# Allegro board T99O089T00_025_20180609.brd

Outline 313.5 x 215.83 mm; copper layers: TOP, G02, T03, G04, T05, G06, T07, G08, P09, P10, G11, P12, G13, T14, G15, T16, G17, T18, G19, BOTTOM. Coordinates in mm from the lower left corner of the outline.
Outline path: 0,208.98 0,1 arc(0.29,0.29) 1,0 41.54,0 arc(42.24,0.29) 42.54,1 42.54,9.63 arc(42.83,10.34) 43.54,10.63 62.46,10.63 arc(62.8,11.22) 63.44,11.45 80.91,11.45 arc(81.61,11.16) 81.91,10.45 81.91,4.6 arc(82.2,3.89) 82.91,3.6 289.06,3.6 289.06,3.97 312.5,3.97 arc(313.21,4.26) 313.5,4.97 313.5,10.05 312.88,10.05 arc(312.53,10.2) 312.38,10.55 312.38,13.05 arc(312.53,13.4) 312.88,13.55 313.5,13.55 313.5,214.83 arc(313.21,215.54) 312.5,215.83 40.49,215.83 arc(39.78,215.54) 39.49,214.83 39.49,210.98 arc(39.19,210.27) 38.49,209.98 1,209.98 arc(0.29,209.69) 0,208.98 ; 288.24,13.05 arc(288.38,13.4) 288.74,13.55 290.24,13.55 arc(290.59,13.4) 290.74,13.05 290.74,10.55 arc(290.59,10.2) 290.24,10.05 288.74,10.05 arc(288.38,10.2) 288.24,10.55 288.24,13.05 ; 296.06,9.09 arc(296.76,9.79) 297.46,9.09 297.46,7.93 arc(296.76,7.24) 296.06,7.93 296.06,9.09 ; 305.66,9.09 arc(306.36,9.79) 307.06,9.09 307.06,7.93 arc(306.36,7.23) 305.66,7.93 305.66,9.09

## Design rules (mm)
net group BITS_T1_RRING: nets BITS_T1_RRING BITS_T1_RRING_XFMR
net group BITS_T1_RTIP: nets BITS_T1_RTIP BITS_T1_RTIP_XFMR
net group BITS_T1_TRING: nets BITS_T1_TRING BITS_T1_TRING_XFMR
net group BITS_T1_TRING_CMC: nets BITS_T1_TRING_CMC BITS_T1_TRING_CONN
net group BITS_T1_TTIP: nets BITS_T1_TTIP BITS_T1_TTIP_XFMR
net group BITS_T1_TTIP_CMC: nets BITS_T1_TTIP_CMC BITS_T1_TTIP_CONN
net group CAUI4_MAC_TO_PHY3_D0: nets CAUI4_MAC_TO_PHY3_DN0 CAUI4_MAC_TO_PHY3_DP0
net group CAUI4_MAC_TO_PHY3_D1: nets CAUI4_MAC_TO_PHY3_DN1 CAUI4_MAC_TO_PHY3_DP1
net group CAUI4_MAC_TO_PHY3_D2: nets CAUI4_MAC_TO_PHY3_DN2 CAUI4_MAC_TO_PHY3_DP2
net group CAUI4_MAC_TO_PHY3_D3: nets CAUI4_MAC_TO_PHY3_DN3 CAUI4_MAC_TO_PHY3_DP3
net group CAUI4_MAC_TO_PHY3_D4: nets CAUI4_MAC_TO_PHY3_DN4 CAUI4_MAC_TO_PHY3_DP4
net group CAUI4_MAC_TO_PHY3_D5: nets CAUI4_MAC_TO_PHY3_DN5 CAUI4_MAC_TO_PHY3_DP5
net group CAUI4_MAC_TO_PHY3_D6: nets CAUI4_MAC_TO_PHY3_DN6 CAUI4_MAC_TO_PHY3_DP6
net group CAUI4_MAC_TO_PHY3_D7: nets CAUI4_MAC_TO_PHY3_DN7 CAUI4_MAC_TO_PHY3_DP7
net group CAUI4_PHY3_TO_MAC_D0: nets CAUI4_PHY3_TO_MAC_DN0 CAUI4_PHY3_TO_MAC_DP0
net group CAUI4_PHY3_TO_MAC_D1: nets CAUI4_PHY3_TO_MAC_DN1 CAUI4_PHY3_TO_MAC_DP1
net group CAUI4_PHY3_TO_MAC_D2: nets CAUI4_PHY3_TO_MAC_DN2 CAUI4_PHY3_TO_MAC_DP2
net group CAUI4_PHY3_TO_MAC_D3: nets CAUI4_PHY3_TO_MAC_DN3 CAUI4_PHY3_TO_MAC_DP3
net group CAUI4_PHY3_TO_MAC_D4: nets CAUI4_PHY3_TO_MAC_DN4 CAUI4_PHY3_TO_MAC_DP4
net group CAUI4_PHY3_TO_MAC_D5: nets CAUI4_PHY3_TO_MAC_DN5 CAUI4_PHY3_TO_MAC_DP5
net group CAUI4_PHY3_TO_MAC_D6: nets CAUI4_PHY3_TO_MAC_DN6 CAUI4_PHY3_TO_MAC_DP6
net group CAUI4_PHY3_TO_MAC_D7: nets CAUI4_PHY3_TO_MAC_DN7 CAUI4_PHY3_TO_MAC_DP7
net group CAUI4_PHY3_TO_QSFP28_D0: nets CAUI4_PHY3_TO_QSFP28_DN0 CAUI4_PHY3_TO_QSFP28_DP0
net group CAUI4_PHY3_TO_QSFP28_D1: nets CAUI4_PHY3_TO_QSFP28_DN1 CAUI4_PHY3_TO_QSFP28_DP1
net group CAUI4_PHY3_TO_QSFP28_D2: nets CAUI4_PHY3_TO_QSFP28_DN2 CAUI4_PHY3_TO_QSFP28_DP2
net group CAUI4_PHY3_TO_QSFP28_D3: nets CAUI4_PHY3_TO_QSFP28_DN3 CAUI4_PHY3_TO_QSFP28_DP3
net group CAUI4_PHY3_TO_QSFP28_D4: nets CAUI4_PHY3_TO_QSFP28_DN4 CAUI4_PHY3_TO_QSFP28_DP4
net group CAUI4_PHY3_TO_QSFP28_D5: nets CAUI4_PHY3_TO_QSFP28_DN5 CAUI4_PHY3_TO_QSFP28_DP5
net group CAUI4_PHY3_TO_QSFP28_D6: nets CAUI4_PHY3_TO_QSFP28_DN6 CAUI4_PHY3_TO_QSFP28_DP6
net group CAUI4_PHY3_TO_QSFP28_D7: nets CAUI4_PHY3_TO_QSFP28_DN7 CAUI4_PHY3_TO_QSFP28_DP7
net group CAUI4_QSFP28_TO_PHY3_D0: nets CAUI4_QSFP28_TO_PHY3_DN0 CAUI4_QSFP28_TO_PHY3_DP0
net group CAUI4_QSFP28_TO_PHY3_D1: nets CAUI4_QSFP28_TO_PHY3_DN1 CAUI4_QSFP28_TO_PHY3_DP1
net group CAUI4_QSFP28_TO_PHY3_D2: nets CAUI4_QSFP28_TO_PHY3_DN2 CAUI4_QSFP28_TO_PHY3_DP2
net group CAUI4_QSFP28_TO_PHY3_D3: nets CAUI4_QSFP28_TO_PHY3_DN3 CAUI4_QSFP28_TO_PHY3_DP3
net group CAUI4_QSFP28_TO_PHY3_D4: nets CAUI4_QSFP28_TO_PHY3_DN4 CAUI4_QSFP28_TO_PHY3_DP4
net group CAUI4_QSFP28_TO_PHY3_D5: nets CAUI4_QSFP28_TO_PHY3_DN5 CAUI4_QSFP28_TO_PHY3_DP5
net group CAUI4_QSFP28_TO_PHY3_D6: nets CAUI4_QSFP28_TO_PHY3_DN6 CAUI4_QSFP28_TO_PHY3_DP6
net group CAUI4_QSFP28_TO_PHY3_D7: nets CAUI4_QSFP28_TO_PHY3_DN7 CAUI4_QSFP28_TO_PHY3_DP7
net group CLK_1PPS_SMA_IN: nets CLK_1PPS_SMA_IN CLK_1PPS_SMA_IN_DN
net group CLK_1PPS_TOD_IN: nets CLK_1PPS_TOD_IN CLK_1PPS_TOD_IN_DN
net group CLK_25M_MAC_TSPLL_DPLL_DN: nets CLK_25M_MAC_TSPLL_DPLL_DN N76605922
net group CLK_25M_MAC_TSPLL_DPLL_DP: nets CLK_25M_MAC_TSPLL_DPLL_DP N76605919
net group CLK_100M_BMC_PCIE_REF_DN: nets CLK_100M_BMC_PCIE_DN CLK_100M_BMC_PCIE_REF_DN
net group CLK_100M_BMC_PCIE_REF_DP: nets CLK_100M_BMC_PCIE_DP CLK_100M_BMC_PCIE_REF_DP
net group CLK_100M_CPU_PCIE_D: nets CLK_100M_CPU_PCIE_DN CLK_100M_CPU_PCIE_DP
net group CLK_100M_MAC_DDR_DN: nets CLK_100M_MAC_DDR_DN N70523859
net group CLK_100M_MAC_DDR_DP: nets CLK_100M_MAC_DDR_DP N70523844
net group CLK_100M_MAC_DDR_OSC_D: nets CLK_100M_MAC_DDR_OSC_DN CLK_100M_MAC_DDR_OSC_DP
net group CLK_100M_MAC_PCIE_DN: nets CLK_100M_MAC_PCIE_DN N72722010
net group CLK_100M_MAC_PCIE_DP: nets CLK_100M_MAC_PCIE_DP N72721990
net group CLK_100M_NIC1_PCIE_DN: nets CLK_100M_NIC1_PCIE_DN N72858667
net group CLK_100M_NIC1_PCIE_DP: nets CLK_100M_NIC1_PCIE_DP N72858665
net group CLK_156M25_PHY_REF0_DN: nets CLK_156M25_OUT3_REF0_DN CLK_156M25_PHY_REF0_DN
net group CLK_156M25_PHY_REF0_DP: nets CLK_156M25_OUT3_REF0_DP CLK_156M25_PHY_REF0_DP
net group CLK_156M25_PHY_REF1_DN: nets CLK_156M25_PHY_REF1_DN N73978233
net group CLK_156M25_PHY_REF1_DP: nets CLK_156M25_PHY_REF1_DP N73978235
net group CLK_PHY1_SYNCE_RCVD2_DN: nets CLK_PHY1_SYNCE_RCVD2_DN CLK_PHY1_SYNCE_REFCLK2_DN
net group CLK_PHY1_SYNCE_RCVD2_DP: nets CLK_PHY1_SYNCE_RCVD2_DP CLK_PHY1_SYNCE_REFCLK2_DP
net group CLK_PHY1_SYNCE_RCVD_DN: nets CLK_PHY1_SYNCE_RCVD_DN CLK_PHY1_SYNCE_REFCLK_DN
net group CLK_PHY1_SYNCE_RCVD_DP: nets CLK_PHY1_SYNCE_RCVD_DP CLK_PHY1_SYNCE_REFCLK_DP
net group CLK_PHY3_SYNCE_RCVDA_DN: nets CLK_PHY3_SYNCE_RCVDA_DN CLK_PHY3_SYNCE_REFCLK1_DN
net group CLK_PHY3_SYNCE_RCVDA_DP: nets CLK_PHY3_SYNCE_RCVDA_DP CLK_PHY3_SYNCE_REFCLK1_DP
net group CLK_PHY3_SYNCE_RCVDB_D: nets CLK_PHY3_SYNCE_RCVDB_DN CLK_PHY3_SYNCE_RCVDB_DP
net group DDR3_BCM_CLK_DN0: nets DDR3_BMC_CLK_DN0 DDR3_BMC_CLK_DP0
net group DDR3_BCM_DQS_DN0: nets DDR3_BMC_DQS_DN0 DDR3_BMC_DQS_DP0
net group DDR3_BCM_DQS_DN1: nets DDR3_BMC_DQS_DN1 DDR3_BMC_DQS_DP1
net group KR_CPU_TO_MAC0: nets KR_CPU_TO_MAC_DN0 KR_CPU_TO_MAC_DP0
net group KR_CPU_TO_MAC1: nets KR_CPU_TO_MAC_DN1 KR_CPU_TO_MAC_DP1
net group KR_IIO_LAN_RX0_DN: nets KR_IIO_LAN_RX0_DN KR_MAC_TO_CPU_DN0
net group KR_IIO_LAN_RX0_DP: nets KR_IIO_LAN_RX0_DP KR_MAC_TO_CPU_DP0
net group KR_IIO_LAN_RX1_DN: nets KR_IIO_LAN_RX1_DN KR_MAC_TO_CPU_DN1
net group KR_IIO_LAN_RX1_DP: nets KR_IIO_LAN_RX1_DP KR_MAC_TO_CPU_DP1
net group MAC_DDRA_CLK: nets MAC_DDRA_CLK_DN MAC_DDRA_CLK_DP
net group MAC_DDRA_DQS0: nets MAC_DDRA_DQS0_DN MAC_DDRA_DQS0_DP
net group MAC_DDRA_DQS1: nets MAC_DDRA_DQS1_DN MAC_DDRA_DQS1_DP
net group MAC_DDRA_DQS2: nets MAC_DDRA_DQS2_DN MAC_DDRA_DQS2_DP
net group MAC_DDRA_DQS3: nets MAC_DDRA_DQS3_DN MAC_DDRA_DQS3_DP
net group MAC_DDRB_CLK: nets MAC_DDRB_CLK_DN MAC_DDRB_CLK_DP
net group MAC_DDRB_DQS0: nets MAC_DDRB_DQS0_DN MAC_DDRB_DQS0_DP
net group MAC_DDRB_DQS1: nets MAC_DDRB_DQS1_DN MAC_DDRB_DQS1_DP
net group MAC_DDRB_DQS2: nets MAC_DDRB_DQS2_DN MAC_DDRB_DQS2_DP
net group MAC_DDRB_DQS3: nets MAC_DDRB_DQS3_DN MAC_DDRB_DQS3_DP
net group MAC_DDRC_CLK: nets MAC_DDRC_CLK_DN MAC_DDRC_CLK_DP
net group MAC_DDRC_DQS0: nets MAC_DDRC_DQS0_DN MAC_DDRC_DQS0_DP
net group MAC_DDRC_DQS1: nets MAC_DDRC_DQS1_DN MAC_DDRC_DQS1_DP
net group MAC_DDRC_DQS2: nets MAC_DDRC_DQS2_DN MAC_DDRC_DQS2_DP
net group MAC_DDRC_DQS3: nets MAC_DDRC_DQS3_DN MAC_DDRC_DQS3_DP
net group MAC_THERM_DIODE_D: nets MAC_THERM_DIODE_DN MAC_THERM_DIODE_DP
net group MDI_NIC1_D0: nets MDI_NIC1_DN0 MDI_NIC1_DP0
net group MDI_NIC1_D1: nets MDI_NIC1_DN1 MDI_NIC1_DP1
net group MDI_NIC1_D2: nets MDI_NIC1_DN2 MDI_NIC1_DP2
net group MDI_NIC1_D3: nets MDI_NIC1_DN3 MDI_NIC1_DP3
net group P3V3_SW: nets N75511258 P3V3_SW
net group P3V3_SW2: nets N75511286 P3V3_SW2
net group PCIE_CPU_IIO_RX_DN0: nets PCIE_CPU_IIO_RX_DN0 PCIE_MAC_TO_CPU_DN
net group PCIE_CPU_IIO_RX_DP0: nets PCIE_CPU_IIO_RX_DP0 PCIE_MAC_TO_CPU_DP
net group PCIE_CPU_PCH_RX_DN0: nets PCIE_BMC_TO_CPU_DN PCIE_CPU_PCH_RX_DN0
net group PCIE_CPU_PCH_RX_DN1: nets PCIE_CPU_PCH_RX_DN1 PCIE_NIC1_TO_CPU_DN
net group PCIE_CPU_PCH_RX_DP0: nets PCIE_BMC_TO_CPU_DP PCIE_CPU_PCH_RX_DP0
net group PCIE_CPU_PCH_RX_DP1: nets PCIE_CPU_PCH_RX_DP1 PCIE_NIC1_TO_CPU_DP
net group PCIE_CPU_TO_BMC_D: nets PCIE_CPU_TO_BMC_DN PCIE_CPU_TO_BMC_DP
net group PCIE_CPU_TO_MAC_D: nets PCIE_CPU_TO_MAC_DN PCIE_CPU_TO_MAC_DP
net group PCIE_CPU_TO_NIC1_D: nets PCIE_CPU_TO_NIC1_DN PCIE_CPU_TO_NIC1_DP
net group PCIE_CPU_TX_D4: nets TP_PCIE_IIO_TO_MB_TX2_DN TP_PCIE_IIO_TO_MB_TX2_DP
net group PCIE_CPU_TX_D5: nets TP_PCIE_IIO_TO_MB_TX3_DN TP_PCIE_IIO_TO_MB_TX3_DP
net group PD_NIF_SRD_REFCLK_Q00_D: nets PD_NIF_SRD_REFCLK_Q00_DN PD_NIF_SRD_REFCLK_Q00_DP
net group PD_NIFE_SRD_REFCLK_Q05_D: nets PD_NIFE_SRD_REFCLK_Q05_DN PD_NIFE_SRD_REFCLK_Q05_DP
net group PTP_1PPS_RS422_CONN_D: nets PTP_1PPS_RS422_CONN_DN PTP_1PPS_RS422_CONN_DP
net group PTP_1PPS_RS422_D: nets PTP_1PPS_RS422_DN PTP_1PPS_RS422_DP
net group PTP_1PPS_RS422_RL_D: nets PTP_1PPS_RS422_RL_DN PTP_1PPS_RS422_RL_DP
net group PTP_TOD_RS422_CONN_D: nets PTP_TOD_RS422_CONN_DN PTP_TOD_RS422_CONN_DP
net group PTP_TOD_RS422_D: nets PTP_TOD_RS422_DN PTP_TOD_RS422_DP
net group PTP_TOD_RS422_RL_D: nets PTP_TOD_RS422_RL_DN PTP_TOD_RS422_RL_DP
net group RJ11-40MIL: nets N77609229 N77609387
net group SFI_PHY1_TO_SFP_D0: nets SFI_PHY1_TO_SFP_DN0 SFI_PHY1_TO_SFP_DP0
net group SFI_PHY1_TO_SFP_D1: nets SFI_PHY1_TO_SFP_DN1 SFI_PHY1_TO_SFP_DP1
net group SFI_PHY1_TO_SFP_D2: nets SFI_PHY1_TO_SFP_DN2 SFI_PHY1_TO_SFP_DP2
net group SFI_PHY1_TO_SFP_D3: nets SFI_PHY1_TO_SFP_DN3 SFI_PHY1_TO_SFP_DP3
net group SFI_PHY1_TO_SFP_D4: nets SFI_PHY1_TO_SFP_DN4 SFI_PHY1_TO_SFP_DP4
net group SFI_PHY1_TO_SFP_D5: nets SFI_PHY1_TO_SFP_DN5 SFI_PHY1_TO_SFP_DP5
net group SFI_PHY1_TO_SFP_D6: nets SFI_PHY1_TO_SFP_DN6 SFI_PHY1_TO_SFP_DP6
net group SFI_PHY1_TO_SFP_D7: nets SFI_PHY1_TO_SFP_DN7 SFI_PHY1_TO_SFP_DP7
net group SFI_SFP_TO_PHY1_D0: nets SFI_SFP_TO_PHY1_DN0 SFI_SFP_TO_PHY1_DP0
net group SFI_SFP_TO_PHY1_D1: nets SFI_SFP_TO_PHY1_DN1 SFI_SFP_TO_PHY1_DP1
net group SFI_SFP_TO_PHY1_D2: nets SFI_SFP_TO_PHY1_DN2 SFI_SFP_TO_PHY1_DP2
net group SFI_SFP_TO_PHY1_D3: nets SFI_SFP_TO_PHY1_DN3 SFI_SFP_TO_PHY1_DP3
net group SFI_SFP_TO_PHY1_D4: nets SFI_SFP_TO_PHY1_DN4 SFI_SFP_TO_PHY1_DP4
net group SFI_SFP_TO_PHY1_D5: nets SFI_SFP_TO_PHY1_DN5 SFI_SFP_TO_PHY1_DP5
net group SFI_SFP_TO_PHY1_D6: nets SFI_SFP_TO_PHY1_DN6 SFI_SFP_TO_PHY1_DP6
net group SFI_SFP_TO_PHY1_D7: nets SFI_SFP_TO_PHY1_DN7 SFI_SFP_TO_PHY1_DP7
net group TP_PCIE_CPU_IIO_RX_2: nets TP_PCIE_CPU_IIO_RX_DN2 TP_PCIE_CPU_IIO_RX_DP2
net group TP_PCIE_CPU_IIO_RX_3: nets TP_PCIE_CPU_IIO_RX_DN3 TP_PCIE_CPU_IIO_RX_DP3
net group TP_PCIE_IIO_TO_MB_TX1_D: nets TP_PCIE_IIO_TO_MB_TX1_DN TP_PCIE_IIO_TO_MB_TX1_DP
net group USB2_PCH_P0_D: nets USB2_PCH_P0_DN USB2_PCH_P0_DP
net group USB2_PCH_P1_DN: nets N83584392 USB2_PCH_P1_DN
net group USB2_PCH_P1_DP: nets N83584389 USB2_PCH_P1_DP
net group USB2_PCH_P3_DN: nets USB2_BMC_HDN USB2_PCH_P3_DN
net group USB2_PCH_P3_DP: nets USB2_BMC_HDP USB2_PCH_P3_DP
net group USB11_BMC_HD: nets USB11_BMC_HDN USB11_BMC_HDP
net group USB_PCH_P2_D: nets USB_PCH_P2_DN USB_PCH_P2_DP
net group USB_PORT_DN: nets N72480405 USB_PORT_DN
net group USB_PORT_DP: nets N72480397 USB_PORT_DP
net group VDD_CORE_VS: nets VDD_CORE_VSN VDD_CORE_VSP
net group XFI_MAC_TO_PHY1_D0: nets XFI_MAC_TO_PHY1_DN0 XFI_MAC_TO_PHY1_DP0
net group XFI_MAC_TO_PHY1_D1: nets XFI_MAC_TO_PHY1_DN1 XFI_MAC_TO_PHY1_DP1
net group XFI_MAC_TO_PHY1_D2: nets XFI_MAC_TO_PHY1_DN2 XFI_MAC_TO_PHY1_DP2
net group XFI_MAC_TO_PHY1_D3: nets XFI_MAC_TO_PHY1_DN3 XFI_MAC_TO_PHY1_DP3
net group XFI_MAC_TO_PHY1_D4: nets XFI_MAC_TO_PHY1_DN4 XFI_MAC_TO_PHY1_DP4
net group XFI_MAC_TO_PHY1_D5: nets XFI_MAC_TO_PHY1_DN5 XFI_MAC_TO_PHY1_DP5
net group XFI_MAC_TO_PHY1_D6: nets XFI_MAC_TO_PHY1_DN6 XFI_MAC_TO_PHY1_DP6
net group XFI_MAC_TO_PHY1_D7: nets XFI_MAC_TO_PHY1_DN7 XFI_MAC_TO_PHY1_DP7
net group XFI_MAC_TO_SFP_D8: nets XFI_MAC_TO_SFP_DN8 XFI_MAC_TO_SFP_DP8
net group XFI_MAC_TO_SFP_D9: nets XFI_MAC_TO_SFP_DN9 XFI_MAC_TO_SFP_DP9
net group XFI_MAC_TO_SFP_D10: nets XFI_MAC_TO_SFP_DN10 XFI_MAC_TO_SFP_DP10
net group XFI_MAC_TO_SFP_D11: nets XFI_MAC_TO_SFP_DN11 XFI_MAC_TO_SFP_DP11
net group XFI_MAC_TO_SFP_D12: nets XFI_MAC_TO_SFP_DN12 XFI_MAC_TO_SFP_DP12
net group XFI_MAC_TO_SFP_D13: nets XFI_MAC_TO_SFP_DN13 XFI_MAC_TO_SFP_DP13
net group XFI_MAC_TO_SFP_D14: nets XFI_MAC_TO_SFP_DN14 XFI_MAC_TO_SFP_DP14
net group XFI_MAC_TO_SFP_D15: nets XFI_MAC_TO_SFP_DN15 XFI_MAC_TO_SFP_DP15
net group XFI_MAC_TO_SFP_D16: nets XFI_MAC_TO_SFP_DN16 XFI_MAC_TO_SFP_DP16
net group XFI_MAC_TO_SFP_D17: nets XFI_MAC_TO_SFP_DN17 XFI_MAC_TO_SFP_DP17
net group XFI_MAC_TO_SFP_D18: nets XFI_MAC_TO_SFP_DN18 XFI_MAC_TO_SFP_DP18
net group XFI_MAC_TO_SFP_D19: nets XFI_MAC_TO_SFP_DN19 XFI_MAC_TO_SFP_DP19
net group XFI_MAC_TO_SFP_D20: nets XFI_MAC_TO_SFP_DN20 XFI_MAC_TO_SFP_DP20
net group XFI_MAC_TO_SFP_D21: nets XFI_MAC_TO_SFP_DN21 XFI_MAC_TO_SFP_DP21
net group XFI_MAC_TO_SFP_D22: nets XFI_MAC_TO_SFP_DN22 XFI_MAC_TO_SFP_DP22
net group XFI_MAC_TO_SFP_D23: nets XFI_MAC_TO_SFP_DN23 XFI_MAC_TO_SFP_DP23
net group XFI_MAC_TO_SFP_DN24: nets XFI_MAC_TO_SFP_DN24 XFI_MAC_TO_SFP_DP24
net group XFI_MAC_TO_SFP_DN25: nets XFI_MAC_TO_SFP_DN25 XFI_MAC_TO_SFP_DP25
net group XFI_MAC_TO_SFP_DN26: nets XFI_MAC_TO_SFP_DN26 XFI_MAC_TO_SFP_DP26
net group XFI_MAC_TO_SFP_DN27: nets XFI_MAC_TO_SFP_DN27 XFI_MAC_TO_SFP_DP27
net group XFI_PHY1_TO_MAC_D0: nets XFI_PHY1_TO_MAC_DN0 XFI_PHY1_TO_MAC_DP0
net group XFI_PHY1_TO_MAC_D1: nets XFI_PHY1_TO_MAC_DN1 XFI_PHY1_TO_MAC_DP1
net group XFI_PHY1_TO_MAC_D2: nets XFI_PHY1_TO_MAC_DN2 XFI_PHY1_TO_MAC_DP2
net group XFI_PHY1_TO_MAC_D3: nets XFI_PHY1_TO_MAC_DN3 XFI_PHY1_TO_MAC_DP3
net group XFI_PHY1_TO_MAC_D4: nets XFI_PHY1_TO_MAC_DN4 XFI_PHY1_TO_MAC_DP4
net group XFI_PHY1_TO_MAC_D5: nets XFI_PHY1_TO_MAC_DN5 XFI_PHY1_TO_MAC_DP5
net group XFI_PHY1_TO_MAC_D6: nets XFI_PHY1_TO_MAC_DN6 XFI_PHY1_TO_MAC_DP6
net group XFI_PHY1_TO_MAC_D7: nets XFI_PHY1_TO_MAC_DN7 XFI_PHY1_TO_MAC_DP7
net group XFI_SFP_TO_MAC_D8: nets XFI_SFP_TO_MAC_DN8 XFI_SFP_TO_MAC_DP8
net group XFI_SFP_TO_MAC_D9: nets XFI_SFP_TO_MAC_DN9 XFI_SFP_TO_MAC_DP9
net group XFI_SFP_TO_MAC_D10: nets XFI_SFP_TO_MAC_DN10 XFI_SFP_TO_MAC_DP10
net group XFI_SFP_TO_MAC_D11: nets XFI_SFP_TO_MAC_DN11 XFI_SFP_TO_MAC_DP11
net group XFI_SFP_TO_MAC_D12: nets XFI_SFP_TO_MAC_DN12 XFI_SFP_TO_MAC_DP12
net group XFI_SFP_TO_MAC_D13: nets XFI_SFP_TO_MAC_DN13 XFI_SFP_TO_MAC_DP13
net group XFI_SFP_TO_MAC_D14: nets XFI_SFP_TO_MAC_DN14 XFI_SFP_TO_MAC_DP14
net group XFI_SFP_TO_MAC_D15: nets XFI_SFP_TO_MAC_DN15 XFI_SFP_TO_MAC_DP15
net group XFI_SFP_TO_MAC_D16: nets XFI_SFP_TO_MAC_DN16 XFI_SFP_TO_MAC_DP16
net group XFI_SFP_TO_MAC_D17: nets XFI_SFP_TO_MAC_DN17 XFI_SFP_TO_MAC_DP17
net group XFI_SFP_TO_MAC_D18: nets XFI_SFP_TO_MAC_DN18 XFI_SFP_TO_MAC_DP18
net group XFI_SFP_TO_MAC_D19: nets XFI_SFP_TO_MAC_DN19 XFI_SFP_TO_MAC_DP19
net group XFI_SFP_TO_MAC_D20: nets XFI_SFP_TO_MAC_DN20 XFI_SFP_TO_MAC_DP20
net group XFI_SFP_TO_MAC_D21: nets XFI_SFP_TO_MAC_DN21 XFI_SFP_TO_MAC_DP21
net group XFI_SFP_TO_MAC_D22: nets XFI_SFP_TO_MAC_DN22 XFI_SFP_TO_MAC_DP22
net group XFI_SFP_TO_MAC_D23: nets XFI_SFP_TO_MAC_DN23 XFI_SFP_TO_MAC_DP23
net group XFI_SFP_TO_MAC_DN24: nets XFI_SFP_TO_MAC_DN24 XFI_SFP_TO_MAC_DP24
net group XFI_SFP_TO_MAC_DN25: nets XFI_SFP_TO_MAC_DN25 XFI_SFP_TO_MAC_DP25
net group XFI_SFP_TO_MAC_DN26: nets XFI_SFP_TO_MAC_DN26 XFI_SFP_TO_MAC_DP26
net group XFI_SFP_TO_MAC_DN27: nets XFI_SFP_TO_MAC_DN27 XFI_SFP_TO_MAC_DP27
net group 3W: nets BITS_CLK_SEL0 BITS_CLK_SEL1 BITS_CLK_SEL2 BITS_SPI_MODE_EN BMC_ROMA0 BMC_ROMA1 BMC_ROMA2 BMC_ROMA3 BMC_ROMA4 BMC_ROMA5 BMC_ROMA6 BMC_ROMA7 BMC_ROMA8 BMC_ROMA9 BMC_ROMA10 BMC_ROMA11 BMC_ROMA12 BMC_ROMA13 BMC_ROMA14 BMC_ROMA15 BMC_ROMA16 BMC_ROMA17 BMC_ROMA18 BMC_ROMA19 BMC_ROMA20 BMC_ROMA21 BMC_ROMA22 BMC_ROMA23 BMC_ROMCS0_N BMC_ROMD0 BMC_ROMD1 BMC_ROMD5 BMC_ROMD6 BMC_ROMD7 BMC_SIOS3_N BMC_SIOS5_N BMC_SIOSPWRREQ_N CPLD_CONF_DONE CPLD_CONFIG_EN CPLD_CRC_ERROR CPLD_STATUS_N EEPROM_ADDR0 EEPROM_ADDR0_SYS EEPROM_ADDR1 EEPROM_ADDR1_SYS EEPROM_WP EEPROM_WP_SYS FAN1_PRSNT_N FAN1_PWM_CTRL FAN1_TACH_INT_INLET FAN1_TACH_INT_INLET_N FAN2_PRSNT_N FAN2_PWM_CTRL FAN2_TACH_INT_INLET FAN2_TACH_INT_INLET_N FAN3_PWM_CTRL FAN3_TACH_INT_INLET FAN3_TACH_INT_INLET_N FAN4_TACH_INT_INLET FAN4_TACH_INT_INLET_N FAN5_TACH_IN FAN5_TACH_INT_INLET FAN5_TACH_INT_INLET_N HWM_FAN1_PRSNT_N HWM_FAN1_PWM_CTRL HWM_FAN2_PRSNT_N HWM_FAN2_PWM_CTRL HWM_FAN3_PWM_CTRL HWM_FAN5_TACH_IN IN_SEL0 IN_SEL1 JITTER_A0 JITTER_A1 JTAG_BITS_RST_N JTAG_BMC_RST_N JTAG_BMC_RTCK JTAG_BMC_RTCK_SR JTAG_BMC_TCK JTAG_BMC_TCK_SR JTAG_BMC_TDI JTAG_BMC_TDO JTAG_BMC_TMS JTAG_BMC_TRST_N JTAG_BRCM_OE JTAG_BRCM_RST_N JTAG_BRCM_TDI JTAG_BRCM_TMS JTAG_CHAIN_RST_N JTAG_CHAIN_TCK JTAG_CHAIN_TCK_BUFF JTAG_CHAIN_TDI JTAG_CHAIN_TDO JTAG_CHAIN_TMS JTAG_CPLD_EN JTAG_CPLD_TDI JTAG_CPLD_TDO JTAG_CPLD_TMS JTAG_MAC_TCE JTAG_MAC_TCK JTAG_MAC_TDI JTAG_NIC1_TCK JTAG_NIC1_TDI JTAG_NIC1_TMS JTAG_PHY1_TCK JTAG_PHY1_TDI JTAG_PHY1_TDO JTAG_PHY3_TCK JTAG_PHY3_TDI JTAG_SMU_RST_N MAC_PUC00_COREPLL_FREQ0 MAC_PUC01_COREPLL_FREQ1 MAC_PUC02_COREPLL_FREQ2 MAC_PUC03_COREPLL_FREQ3 MAC_PUC04_PD MAC_PUC05_I2C_ADDR0 MAC_PUC06_I2C_ADDR1 MAC_PUC07_PCIE_DIS MAC_PUC08_PD MAC_PUC09_PD MAC_PUC10_COREPLL_SEL MAC_PUC11_COREPLL_SEL MAC_VCORE_ROV0 MAC_VCORE_ROV1 MAC_VCORE_ROV2 PHY1_PRTAD0 PHY1_PRTAD1 PHY1_PRTAD3 PHY1_PRTAD4 PHY3_PRTAD1 PHY3_PRTAD2 PHY3_PRTAD3 PHY3_PRTAD4 PHY3_SERBOOT UART_BMC_CONSOLE_RX UART_BMC_CONSOLE_RX_OUT UART_BMC_CONSOLE_TX UART_BMC_TO_CPU UART_BMC_TXD1 UART_BMC_TXD5 UART_CPU_BMC_MUX_SEL UART_CPU_CONSOLE_RX UART_CPU_CONSOLE_RX_OUT UART_CPU_CONSOLE_TX UART_CPU_TO_BMC UART_MAC_TX0 UART_MAC_TX1 UART_RS232_RX UART_RS232_RX_IN UART_RS232_RX_RJ45 UART_RS232_RX_USB UART_RS232_TX UART_RS232_TX_OUT UART_RS232_TX_RJ45 UART_RS232_TX_USB UART_TOD_GNSS_RXD UART_TOD_GNSS_TXD UART_TOD_RS422_RXD UART_TOD_RS422_TXD
net group 3W-I2C: nets BITS_REFR BMC_ADCREXT BMC_ADCVREFN BMC_ADCVREFP BMC_DACRSET BMC_I2C9_SCL BMC_OSC_OE BMC_PCIE_REXT BMC_PWRGD BMC_SFLA_CS0_N BMC_SFLA_HOLD_N BMC_SFLA_SCK BMC_SFLA_WP_N BMC_SPI_CS1_N BUILD_ID0 BUILD_ID1 CLK_DDR_SRC_SEL CLK_LPC_OE CLK_NIC1_OSC_OE CPLD_OSC_OE CPU_PRSNT_L CPU_PWRGD CPU_TO_BMC_PWRGD CPU_TO_CPLD_PWRGD HW_REV_ID0 HW_REV_ID1 HWM_JTAG_TRCK HWM_JTAG_TRST_N I2C0_HWM_SCL I2C0_HWM_SDA I2C0_MISC_SCL I2C0_MISC_SDA I2C0_PCH_SCL I2C0_PCH_SDA I2C0_PSU1_SCL I2C0_PSU1_SDA I2C0_PSU2_SCL I2C0_PSU2_SDA I2C0_PWR_SCL I2C0_PWR_SDA I2C0_SYS_SCL I2C0_SYS_SDA I2C1_BMC_SCL I2C1_BMC_SDA I2C2_BMC_SCL I2C2_BMC_SDA I2C2_PCH_SCL I2C2_PCH_SDA I2C3_BMC_SCL I2C3_BMC_SDA I2C4_BMC_SCL I2C4_BMC_SDA I2C_CPLD_SCL I2C_CPLD_SDA I2C_GNSS_SCL I2C_GNSS_SDA I2C_HWM_CLK I2C_HWM_DAT I2C_IOP_ABS0_ADDR0 I2C_IOP_ABS0_ADDR1 I2C_IOP_ABS0_ADDR2 I2C_IOP_ABS0_SCL I2C_IOP_ABS0_SDA I2C_IOP_ABS1_ADDR0 I2C_IOP_ABS1_ADDR1 I2C_IOP_ABS1_ADDR2 I2C_IOP_ABS1_SCL I2C_IOP_ABS1_SDA I2C_IOP_ALRM_ADDR0 I2C_IOP_ALRM_ADDR1 I2C_IOP_ALRM_ADDR2 I2C_IOP_ALRM_SCL I2C_IOP_ALRM_SDA I2C_IOP_DIS0_ADDR0 I2C_IOP_DIS0_ADDR1 I2C_IOP_DIS0_ADDR2 I2C_IOP_DIS0_SCL I2C_IOP_DIS0_SDA I2C_IOP_DIS1_ADDR0 I2C_IOP_DIS1_ADDR1 I2C_IOP_DIS1_ADDR2 I2C_IOP_DIS1_SCL I2C_IOP_DIS1_SDA I2C_IOP_FLT0_ADDR0 I2C_IOP_FLT0_ADDR1 I2C_IOP_FLT0_ADDR2 I2C_IOP_FLT0_SCL I2C_IOP_FLT0_SDA I2C_IOP_FLT1_ADDR0 I2C_IOP_FLT1_ADDR1 I2C_IOP_FLT1_ADDR2 I2C_IOP_FLT1_SCL I2C_IOP_FLT1_SDA I2C_IOP_FLT2_ADDR0 I2C_IOP_FLT2_ADDR1 I2C_IOP_FLT2_ADDR2 I2C_IOP_LOS0_ADDR0 I2C_IOP_LOS0_ADDR1 I2C_IOP_LOS0_ADDR2 I2C_IOP_LOS0_SCL I2C_IOP_LOS0_SDA I2C_IOP_LOS1_ADDR0 I2C_IOP_LOS1_ADDR1 I2C_IOP_LOS1_ADDR2 I2C_IOP_LOS1_SCL I2C_IOP_LOS1_SDA I2C_IOP_QSFP28_SCL I2C_IOP_QSFP28_SDA I2C_IOP_RS0_ADDR0 I2C_IOP_RS0_ADDR1 I2C_IOP_RS0_ADDR2 I2C_IOP_RS0_SCL I2C_IOP_RS0_SDA I2C_IOP_RS1_ADDR0 I2C_IOP_RS1_ADDR1 I2C_IOP_RS1_ADDR2 I2C_IOP_RS1_SCL I2C_IOP_RS1_SDA I2C_IOP_VMG_SCL I2C_IOP_VMG_SDA I2C_MAC_SCL I2C_MAC_SDA I2C_MGMT_MUX1_ADDR0 I2C_MGMT_MUX1_ADDR1 I2C_MGMT_MUX1_ADDR2 I2C_MGMT_MUX1_SCL I2C_MGMT_MUX1_SDA I2C_MGMT_SCL I2C_MGMT_SDA I2C_MUX3_ADDR0 I2C_MUX3_ADDR1 I2C_MUX3_ADDR2 I2C_MUX4_ADDR0 I2C_MUX4_ADDR1 I2C_MUX4_ADDR2 I2C_MUX5_ADDR0 I2C_MUX5_ADDR1 I2C_MUX5_ADDR2 I2C_MUX6_ADDR0 I2C_MUX6_ADDR1 I2C_MUX6_ADDR2 I2C_QSFP28_MUX7_SCL I2C_QSFP28_MUX7_SDA I2C_QSFP28_P1_SCL I2C_QSFP28_P1_SDA I2C_QSFP28_P2_SCL I2C_QSFP28_P2_SDA I2C_QSFP28_P3_SCL I2C_QSFP28_P3_SDA I2C_QSFP28_P4_SCL I2C_QSFP28_P4_SDA I2C_SFP+_MUX2_SCL I2C_SFP+_MUX2_SDA I2C_SFP+_MUX3_SCL I2C_SFP+_MUX3_SDA I2C_SFP+_MUX4_SCL I2C_SFP+_MUX4_SDA I2C_SFP+_MUX5_SCL I2C_SFP+_MUX5_SDA I2C_SFP+_MUX6_SCL I2C_SFP+_MUX6_SDA I2C_SFP+_P00_SCL I2C_SFP+_P00_SDA I2C_SFP+_P01_SCL I2C_SFP+_P01_SDA I2C_SFP+_P02_SCL I2C_SFP+_P02_SDA I2C_SFP+_P03_SCL I2C_SFP+_P03_SDA I2C_SFP+_P04_SCL I2C_SFP+_P04_SDA I2C_SFP+_P05_SCL I2C_SFP+_P05_SDA I2C_SFP+_P06_SCL I2C_SFP+_P06_SDA I2C_SFP+_P07_SCL I2C_SFP+_P07_SDA I2C_SFP+_P08_SCL I2C_SFP+_P08_SDA I2C_SFP+_P09_SCL I2C_SFP+_P09_SDA I2C_SFP+_P10_SCL I2C_SFP+_P10_SDA I2C_SFP+_P11_SCL I2C_SFP+_P11_SDA I2C_SFP+_P12_SCL I2C_SFP+_P12_SDA I2C_SFP+_P13_SCL I2C_SFP+_P13_SDA I2C_SFP+_P14_SCL I2C_SFP+_P14_SDA I2C_SFP+_P15_SCL I2C_SFP+_P15_SDA I2C_SFP+_P16_SCL I2C_SFP+_P16_SDA I2C_SFP+_P17_SCL I2C_SFP+_P17_SDA I2C_SFP+_P18_SCL I2C_SFP+_P18_SDA I2C_SFP+_P19_SCL I2C_SFP+_P19_SDA I2C_SFP+_P20_SCL I2C_SFP+_P20_SDA I2C_SFP+_P21_SCL I2C_SFP+_P21_SDA I2C_SFP+_P22_SCL I2C_SFP+_P22_SDA I2C_SFP+_P23_SCL I2C_SFP+_P23_SDA I2C_SFP+_P24_SCL I2C_SFP+_P24_SDA I2C_SFP+_P25_SCL I2C_SFP+_P25_SDA I2C_SFP+_P26_SCL I2C_SFP+_P26_SDA I2C_SFP+_P27_SCL I2C_SFP+_P27_SDA I2C_SFP_IOP0_SCL I2C_SFP_IOP0_SDA I2C_SFP_IOP1_SCL I2C_SFP_IOP1_SDA I2C_SFP_IOP2_SCL I2C_SFP_IOP2_SDA I2C_SFP_MUX2_ADDR0 I2C_SFP_MUX2_ADDR1 I2C_SFP_MUX2_ADDR2 I2C_SFP_MUX7_ADDR0 I2C_SFP_MUX7_ADDR1 I2C_SFP_MUX7_ADDR2 I2C_SFP_MUX_SCL I2C_SFP_MUX_SDA I2C_SMU_EEPROM_SCL I2C_SMU_EEPROM_SDA I2C_SMU_SCL I2C_SMU_SDA I2C_TSEN1_ADDR0 I2C_TSEN1_ADDR1 I2C_TSEN_SCL I2C_TSEN_SDA INT1_GNSS_N INT_BITS_N INT_BMC_LOAD_DEFAULT_N INT_BMC_TO_CPU_N INT_CHIP_CPLD_TO_CPU_N INT_CJA_INTR_N INT_CJA_LOL_N INT_CPLD_NMI_N INT_CPU_LOAD_DEFAULT_N INT_CPU_TO_BMC_N INT_FAN1_N INT_FAN2_N INT_FAN3_N INT_FAN4_N INT_FAN5_N INT_FAN_CARD_N INT_LOAD_DEFAULT_N INT_MAC_N INT_NIC1_ARLT_N INT_NMI_CPLD_TO_BMC_N INT_NMI_CPLD_TO_CPU_N INT_PHY1_N INT_PHY3_N INT_PSU1_N INT_PSU2_N INT_PTP_CPLD_TO_CPU_N INT_QSFP28_N INT_SFP+_ABS_N0 INT_SFP+_ABS_N1 INT_SFP+_DIS_N0 INT_SFP+_DIS_N1 INT_SFP+_DIS_N2 INT_SFP+_FLT_N0 INT_SFP+_FLT_N1 INT_SFP+_LOS_N0 INT_SFP+_LOS_N1 INT_SFP+_RS_N0 INT_SFP+_RS_N1 INT_SFP_CPLD_TO_CPU_N INT_SMU_N INT_TSEN_NMI_N INT_VCORE_ALRT_N INT_VCORE_VR_FAULT_N LED0_NIC1_LINK_FE LED1_NIC1_ACT_N LED2_NIC1_LINK_GE LED_ETH_STAT_CLR_N LED_FAN_CLR_N LED_FAN_SCL LED_FAN_SCLK LED_FAN_SDA LED_FAN_SDAT LED_INIT_CLR_N LED_MAC_SCLK LED_MAC_SCLK_SR LED_MAC_SDAT LED_MAC_SDAT_SR LED_NIC1_LINK_FE LED_NIC1_LINK_GE LED_PORT_BUF0_EN_N LED_PORT_BUF1_EN_N LED_PORT_CLK0 LED_PORT_CLK1 LED_PORT_CLK2 LED_PORT_CLK3 LED_PORT_CLK4 LED_PORT_CLK5 LED_PORT_CLK6 LED_PORT_CLK7 LED_PORT_CLK8 LED_PORT_CLK9 LED_PORT_CLK10 LED_PORT_CLK_BUF0 LED_PORT_CLK_BUF1 LED_PORT_CLK_BUF2 LED_PORT_CLK_IN0 LED_PORT_CLK_IN1 LED_PORT_CLK_IN2 LED_PORT_CLR_N0 LED_PORT_CLR_N1 LED_PORT_STAT_CLK0 LED_PORT_STAT_CLK1 LED_PORT_STAT_CLK2 LED_PORT_STAT_CLK3 LED_PORT_STAT_CLK4 LED_PORT_STAT_CLK5 LED_PORT_STAT_CLK6 LED_PORT_STAT_CLK7 LED_PORT_STAT_CLK8 LED_PORT_STAT_CLR_N0 LED_PORT_STAT_CLR_N1 LED_QSFP28_GRN_P1 LED_QSFP28_GRN_P2 LED_QSFP28_GRN_P3 LED_QSFP28_GRN_P4 LED_QSFP28_GRN_P5 LED_QSFP28_GRN_P6 LED_QSFP28_GRN_P7 LED_QSFP28_GRN_P8 LED_QSFP28_GRN_SR_P1 LED_QSFP28_GRN_SR_P2 LED_QSFP28_GRN_SR_P3 LED_QSFP28_GRN_SR_P4 LED_QSFP28_GRN_SR_P5 LED_QSFP28_GRN_SR_P6 LED_QSFP28_GRN_SR_P7 LED_QSFP28_GRN_SR_P8 LED_QSFP28_YEL_P1 LED_QSFP28_YEL_P2 LED_QSFP28_YEL_P3 LED_QSFP28_YEL_P4 LED_QSFP28_YEL_P5 LED_QSFP28_YEL_P6 LED_QSFP28_YEL_P7 LED_QSFP28_YEL_P8 LED_QSFP28_YEL_SR_P1 LED_QSFP28_YEL_SR_P2 LED_QSFP28_YEL_SR_P3 LED_QSFP28_YEL_SR_P4 LED_QSFP28_YEL_SR_P5 LED_QSFP28_YEL_SR_P6 LED_QSFP28_YEL_SR_P7 LED_QSFP28_YEL_SR_P8 LED_SFP+_GRN_P0 LED_SFP+_GRN_P1 LED_SFP+_GRN_P2 LED_SFP+_GRN_P3 LED_SFP+_GRN_P4 LED_SFP+_GRN_P5 LED_SFP+_GRN_P6 LED_SFP+_GRN_P7 LED_SFP+_GRN_P8 LED_SFP+_GRN_P9 LED_SFP+_GRN_P10 LED_SFP+_GRN_P11 LED_SFP+_GRN_P12 LED_SFP+_GRN_P13 LED_SFP+_GRN_P14 LED_SFP+_GRN_P15 LED_SFP+_GRN_P16 LED_SFP+_GRN_P17 LED_SFP+_GRN_P18 LED_SFP+_GRN_P19 LED_SFP+_GRN_P20 LED_SFP+_GRN_P21 LED_SFP+_GRN_P22 LED_SFP+_GRN_P23 LED_SFP+_GRN_P24 LED_SFP+_GRN_P25 LED_SFP+_GRN_P26 LED_SFP+_GRN_P27 LED_SFP+_GRN_SR_P0 LED_SFP+_GRN_SR_P1 LED_SFP+_GRN_SR_P2 LED_SFP+_GRN_SR_P3 LED_SFP+_GRN_SR_P4 LED_SFP+_GRN_SR_P5 LED_SFP+_GRN_SR_P6 LED_SFP+_GRN_SR_P7 LED_SFP+_GRN_SR_P8 LED_SFP+_GRN_SR_P9 LED_SFP+_GRN_SR_P10 LED_SFP+_GRN_SR_P11 LED_SFP+_GRN_SR_P12 LED_SFP+_GRN_SR_P13 LED_SFP+_GRN_SR_P14 LED_SFP+_GRN_SR_P15 LED_SFP+_GRN_SR_P16 LED_SFP+_GRN_SR_P17 LED_SFP+_GRN_SR_P18 LED_SFP+_GRN_SR_P19 LED_SFP+_GRN_SR_P20 LED_SFP+_GRN_SR_P21 LED_SFP+_GRN_SR_P22 LED_SFP+_GRN_SR_P23 LED_SFP+_GRN_SR_P24 LED_SFP+_GRN_SR_P25 LED_SFP+_GRN_SR_P26 LED_SFP+_GRN_SR_P27 LED_SFP+_YEL_P0 LED_SFP+_YEL_P1 LED_SFP+_YEL_P2 LED_SFP+_YEL_P3 LED_SFP+_YEL_P4 LED_SFP+_YEL_P5 LED_SFP+_YEL_P6 LED_SFP+_YEL_P7 LED_SFP+_YEL_P8 LED_SFP+_YEL_P9 LED_SFP+_YEL_P10 LED_SFP+_YEL_P11 LED_SFP+_YEL_P12 LED_SFP+_YEL_P13 LED_SFP+_YEL_P14 LED_SFP+_YEL_P15 LED_SFP+_YEL_P16 LED_SFP+_YEL_P17 LED_SFP+_YEL_P18 LED_SFP+_YEL_P19 LED_SFP+_YEL_P20 LED_SFP+_YEL_P21 LED_SFP+_YEL_P22 LED_SFP+_YEL_P23 LED_SFP+_YEL_P24 LED_SFP+_YEL_P25 LED_SFP+_YEL_P26 LED_SFP+_YEL_P27 LED_SFP+_YEL_SR_P0 LED_SFP+_YEL_SR_P1 LED_SFP+_YEL_SR_P2 LED_SFP+_YEL_SR_P3 LED_SFP+_YEL_SR_P4 LED_SFP+_YEL_SR_P5 LED_SFP+_YEL_SR_P6 LED_SFP+_YEL_SR_P7 LED_SFP+_YEL_SR_P8 LED_SFP+_YEL_SR_P9 LED_SFP+_YEL_SR_P10 LED_SFP+_YEL_SR_P11 LED_SFP+_YEL_SR_P12 LED_SFP+_YEL_SR_P13 LED_SFP+_YEL_SR_P14 LED_SFP+_YEL_SR_P15 LED_SFP+_YEL_SR_P16 LED_SFP+_YEL_SR_P17 LED_SFP+_YEL_SR_P18 LED_SFP+_YEL_SR_P19 LED_SFP+_YEL_SR_P20 LED_SFP+_YEL_SR_P21 LED_SFP+_YEL_SR_P22 LED_SFP+_YEL_SR_P23 LED_SFP+_YEL_SR_P24 LED_SFP+_YEL_SR_P25 LED_SFP+_YEL_SR_P26 LED_SFP+_YEL_SR_P27 LED_SYS_STAT_CLR_N LED_SYS_STAT_SCL LED_SYS_STAT_SCLK LED_SYS_STAT_SDA LED_SYS_STAT_SDAT LPC_BMC_FRAME_N LPC_BMC_LAD0 LPC_BMC_LAD1 LPC_BMC_LAD2 LPC_BMC_LAD3 LPC_BMC_SERIRQ_N LPC_FRAME_PCH_N LPC_LAD0_PCH LPC_LAD1_PCH LPC_LAD2_PCH LPC_LAD3_PCH LPC_PDN_N LPC_PME_N LPC_SERIRQ_PCH_N MAC_RES_CAL0 MAC_RES_CAL1 MIIM_BMC1_MDC MIIM_BMC1_MDIO MIIM_BMC2_MDC MIIM_BMC2_MDIO MIIM_MAC_ST_MDC0 MIIM_MAC_ST_MDC1 MIIM_MAC_ST_MDC2 MIIM_MAC_ST_MDIO0 MIIM_MAC_ST_MDIO2 MIIM_PHY1_MDC MIIM_PHY1_MDIO MIIM_PHY2_MDC MIIM_PHY3_MDC MIIM_PHY3_MDIO NCSI_BMC_CSRDV NCSI_BMC_RXD0 NCSI_BMC_RXD1 NCSI_BMC_TXD0 NCSI_BMC_TXD1 NCSI_BMC_TXEN NCSI_NIC1_CSRDV NCSI_NIC1_RXD0 NCSI_NIC1_RXD1 NIC1_NVM_CLK NIC1_NVM_CLK_ST NIC1_NVM_CS_N NIC1_NVM_CS_ST_N NIC1_NVM_HOLD_N NIC1_NVM_SI NIC1_NVM_SI_ST NIC1_NVM_SO NIC1_NVM_SO_OUT NIC1_NVM_WP_N NIC1_RSET NMI_BMC_TO_CPU_N PCIE_BMC_WAKE_N PCIE_NIC1_WAKE_N PSU1_ALRT_N PSU1_PRSNT_N PSU1_PSON_N PSU1_PWRGD PSU1_PWROK PSU2_ALRT_N PSU2_PRSNT_N PSU2_PSON_N PSU2_PWRGD PSU2_PWROK PTP_1PPS_RS422_RXD_EN_N PTP_1PPS_RS422_RXD_IN PTP_1PPS_RS422_TXD_EN PTP_OSC_OE PTP_TOD_RS422_RXD_EN_N PTP_TOD_RS422_RXD_IN PTP_TOD_RS422_TXD_EN PWR_OFF_MAC PWREN_P1V0 PWREN_P1V2 PWREN_P1V8 PWREN_P1V25 PWREN_P3V3 PWREN_VCORE PWROK_SYS_DC QSFP28_P1_INT_N QSFP28_P1_LPMODE QSFP28_P1_PRSNT_N QSFP28_P1_RST_N QSFP28_P2_INT_N QSFP28_P2_MODSEL_N QSFP28_P2_PRSNT_N QSFP28_P2_RST_N QSFP28_PWR_OC_N QSFP_PWR_ILIM ROV_EN ROV_PG RST_BITS_N RST_BMC_DDR3_N RST_BMC_PCIE_N RST_BMC_SYS_L RST_BMC_TO_CPU_N RST_BMC_WDT_L RST_CJA_N RST_CPLD_TO_BMC_SYS_L RST_CPLD_TO_CPU_N RST_CPU_PWRBTN_N RST_CPU_SYS_N RST_CPU_TO_BMC_N RST_CPU_TO_MB_I2C_N RST_GNSS_N RST_HWM_N RST_I2C_MUX1_N RST_I2C_MUX2_N RST_I2C_MUX3_N RST_I2C_MUX4_N RST_I2C_MUX5_N RST_I2C_MUX6_N RST_I2C_MUX7_N RST_MAC_N RST_NIC1_N RST_NIC1_PCIE_N RST_PHY1_N RST_PHY3_N RST_SMU_N RST_SW_BTN_N RST_SW_TO_CP2104 RST_USB_BRIDGE_N RTC_BAT_SENSE_EN_N SFP28_PWR_OC_N SFP+_P00_MOD_ABS SFP+_P00_RATE_SEL SFP+_P00_RATE_SEL_OUT SFP+_P00_RX_LOS SFP+_P00_TX_DIS SFP+_P00_TX_FLT SFP+_P01_MOD_ABS SFP+_P01_RATE_SEL SFP+_P01_RATE_SEL_OUT SFP+_P01_RX_LOS SFP+_P01_TX_DIS SFP+_P01_TX_FLT SFP+_P02_MOD_ABS SFP+_P02_RATE_SEL SFP+_P02_RATE_SEL_OUT SFP+_P02_RX_LOS SFP+_P02_TX_DIS SFP+_P02_TX_FLT SFP+_P03_MOD_ABS SFP+_P03_RATE_SEL SFP+_P03_RATE_SEL_OUT SFP+_P03_RX_LOS SFP+_P03_TX_DIS SFP+_P03_TX_FLT SFP+_P04_MOD_ABS SFP+_P04_RATE_SEL SFP+_P04_RATE_SEL_OUT SFP+_P04_RX_LOS SFP+_P04_TX_DIS SFP+_P04_TX_FLT SFP+_P05_MOD_ABS SFP+_P05_RATE_SEL SFP+_P05_RATE_SEL_OUT SFP+_P05_RX_LOS SFP+_P05_TX_DIS SFP+_P05_TX_FLT SFP+_P06_MOD_ABS SFP+_P06_RATE_SEL SFP+_P06_RATE_SEL_OUT SFP+_P06_RX_LOS SFP+_P06_TX_DIS SFP+_P06_TX_FLT SFP+_P07_MOD_ABS SFP+_P07_RATE_SEL SFP+_P07_RATE_SEL_OUT SFP+_P07_RX_LOS SFP+_P07_TX_DIS SFP+_P07_TX_FLT SFP+_P08_MOD_ABS SFP+_P08_RATE_SEL SFP+_P08_RATE_SEL_OUT SFP+_P08_RX_LOS SFP+_P08_TX_DIS SFP+_P08_TX_FLT SFP+_P09_MOD_ABS SFP+_P09_RATE_SEL SFP+_P09_RATE_SEL_OUT SFP+_P09_RX_LOS SFP+_P09_TX_DIS SFP+_P09_TX_FLT SFP+_P10_MOD_ABS SFP+_P10_RATE_SEL SFP+_P10_RATE_SEL_OUT SFP+_P10_RX_LOS SFP+_P10_TX_DIS SFP+_P10_TX_FLT SFP+_P11_MOD_ABS SFP+_P11_RATE_SEL SFP+_P11_RATE_SEL_OUT SFP+_P11_RX_LOS SFP+_P11_TX_DIS SFP+_P11_TX_FLT SFP+_P12_MOD_ABS SFP+_P12_RATE_SEL SFP+_P12_RATE_SEL_OUT SFP+_P12_RX_LOS SFP+_P12_TX_DIS SFP+_P12_TX_FLT SFP+_P13_MOD_ABS SFP+_P13_RATE_SEL SFP+_P13_RATE_SEL_OUT SFP+_P13_RX_LOS SFP+_P13_TX_DIS SFP+_P13_TX_FLT SFP+_P14_MOD_ABS SFP+_P14_RATE_SEL SFP+_P14_RATE_SEL_OUT SFP+_P14_RX_LOS SFP+_P14_TX_DIS SFP+_P14_TX_FLT SFP+_P15_MOD_ABS SFP+_P15_RATE_SEL SFP+_P15_RATE_SEL_OUT SFP+_P15_RX_LOS SFP+_P15_TX_DIS SFP+_P15_TX_FLT SFP+_P16_MOD_ABS SFP+_P16_RATE_SEL SFP+_P16_RATE_SEL_OUT SFP+_P16_RX_LOS SFP+_P16_TX_DIS SFP+_P16_TX_FLT SFP+_P17_MOD_ABS SFP+_P17_RATE_SEL SFP+_P17_RATE_SEL_OUT SFP+_P17_RX_LOS SFP+_P17_TX_DIS SFP+_P17_TX_FLT SFP+_P18_MOD_ABS SFP+_P18_RATE_SEL SFP+_P18_RATE_SEL_OUT SFP+_P18_RX_LOS SFP+_P18_TX_DIS SFP+_P18_TX_FLT SFP+_P19_MOD_ABS SFP+_P19_RATE_SEL SFP+_P19_RATE_SEL_OUT SFP+_P19_RX_LOS SFP+_P19_TX_DIS SFP+_P19_TX_FLT SFP+_P20_MOD_ABS SFP+_P20_RATE_SEL SFP+_P20_RATE_SEL_OUT SFP+_P20_RX_LOS SFP+_P20_TX_DIS SFP+_P20_TX_FLT SFP+_P21_MOD_ABS SFP+_P21_RATE_SEL SFP+_P21_RATE_SEL_OUT SFP+_P21_RX_LOS SFP+_P21_TX_DIS SFP+_P21_TX_FLT SFP+_P22_MOD_ABS SFP+_P22_RATE_SEL SFP+_P22_RATE_SEL_OUT SFP+_P22_RX_LOS SFP+_P22_TX_DIS SFP+_P22_TX_FLT SFP+_P23_MOD_ABS SFP+_P23_RATE_SEL SFP+_P23_RATE_SEL_OUT SFP+_P23_RX_LOS SFP+_P23_TX_DIS SFP+_P23_TX_FLT SFP+_P24_MOD_ABS SFP+_P24_RATE_SEL SFP+_P24_RATE_SEL_OUT SFP+_P24_RX_LOS SFP+_P24_TX_DIS SFP+_P24_TX_FLT SFP+_P25_MOD_ABS SFP+_P25_RATE_SEL SFP+_P25_RATE_SEL_OUT SFP+_P25_RX_LOS SFP+_P25_TX_DIS SFP+_P25_TX_FLT SFP+_P26_MOD_ABS SFP+_P26_RATE_SEL SFP+_P26_RATE_SEL_OUT SFP+_P26_RX_LOS SFP+_P26_TX_DIS SFP+_P26_TX_FLT SFP+_P27_MOD_ABS SFP+_P27_RX_LOS SFP+_P27_TX_DIS SFP+_P27_TX_FLT SFP+_PWR_OC_GP1 SFP+_PWR_OC_GP2 SFP+_PWR_OC_GP3 SFP_PWR00_OC_N SFP_PWR01_OC_N SFP_PWR02_OC_N SFP_PWR03_OC_N SFP_PWR04_OC_N SFP_PWR05_OC_N SFP_PWR06_OC_N SFP_PWR07_OC_N SFP_PWR08_OC_N SFP_PWR09_OC_N SFP_PWR10_OC_N SFP_PWR11_OC_N SFP_PWR12_OC_N SFP_PWR13_OC_N SFP_PWR_ILIM00 SFP_PWR_ILIM01 SFP_PWR_ILIM02 SFP_PWR_ILIM03 SFP_PWR_ILIM04 SFP_PWR_ILIM05 SFP_PWR_ILIM06 SFP_PWR_ILIM07 SFP_PWR_ILIM08 SFP_PWR_ILIM09 SFP_PWR_ILIM10 SFP_PWR_ILIM11 SFP_PWR_ILIM12 SFP_PWR_ILIM13 SI5344B_OE_N SKU_ID0 SKU_ID1 SKU_ID2 SKU_ID3 SMB_NIC1_CLK SMB_NIC1_DAT SMU_DPLL1_LOCK SMU_DPLL2_LOCK SMU_DPLL3_LOCK SMU_I2C_ADDR1 SMU_I2C_ADDR2 SMU_INPUT0_LOS_N SMU_INPUT1_LOS_N SMU_INPUT2_LOS_N SMU_INPUT3_LOS_N SMU_MASTER SPI_BITS_CS_N SPI_BITS_MISO SPI_BITS_MOSI SPI_BITS_SCK SPI_BITS_SDI SPI_BITS_SDO SPI_PHY3_CLK SPI_PHY3_CS_N SPI_PHY3_HOLD_N SPI_PHY3_MISO SPI_PHY3_MOSI SPI_PHY3_SCK SPI_PHY3_WP_N SPI_USB_SCK USB2VRES USB_PWR_EN USB_PWR_ILIM USB_PWR_OC_N VBAT_VSENSE_IN VCORE_SENSE_GND VCORE_SENSE_PWR VMG_P1V0_DDR_HIGH VMG_P1V0_DDR_LOW VMG_P1V0_PHY_HIGH VMG_P1V0_PHY_LOW VMG_P1V2_HIGH VMG_P1V2_LOW VMG_P1V8_HIGH VMG_P1V8_LOW VMG_P1V25_HIGH VMG_P1V25_LOW VMG_P2V5_HIGH VMG_P2V5_LOW VMG_P3V3_HIGH VMG_P3V3_LOW VMG_P5V_HIGH VMG_P5V_LOW VSENSE_BMC_P1V26 VSENSE_BMC_P1V538 VSENSE_BMC_P3V3 VTT_DDR_EN VTT_DDR_PG
net group CLK-50OHM: nets CLK_1M544_BITS_IN CLK_1M544_BITS_OSI CLK_1M544_BITS_RCVD CLK_1M544_BITS_RCVD_TSCK CLK_1PPS_GNSS_EXTINT0 CLK_1PPS_GNSS_IN CLK_1PPS_MAC_SYNC_IN0 CLK_1PPS_MAC_SYNC_IN1 CLK_1PPS_SMA1 CLK_1PPS_SMA1_IN CLK_1PPS_SMA2 CLK_1PPS_SMA2_OUT CLK_1PPS_SMA_BUF_IN CLK_1PPS_SMA_OUT CLK_1PPS_SMA_OUT_AMP CLK_1PPS_SMA_OUT_FB CLK_1PPS_TOD_OUT CLK_10M_GNSS_IN CLK_10M_SMA1 CLK_10M_SMA1_IN CLK_10M_SMA2 CLK_10M_SMA2_REL_OUT CLK_10M_SMA_BUF CLK_10M_SMA_BUF_IN CLK_10M_SMA_IN CLK_10M_SMA_OUT CLK_10M_SMA_OUT_AMP CLK_10M_SMA_OUT_FB CLK_25M_5P49V_OUT0 CLK_25M_CPLD_CLK0 CLK_25M_CPLD_OSC CLK_25M_MAC_CLOCK25 CLK_25M_MAC_OSC CLK_25M_MAC_OSC_DN1 CLK_25M_MAC_OSC_DP1 CLK_25M_MAC_TCXO CLK_25M_PCIE_OSC CLK_25M_PCIE_XTALIN CLK_25M_SMU_OCXO CLK_25M_SMU_OCXO_OUT0 CLK_25M_SMU_OCXO_OUT1 CLK_25M_SMU_XTAL_IN0 CLK_25M_SMU_XTAL_OUT0 CLK_25M_SRC_SEL CLK_33M_LPC CLK_33M_LPC_BMC CLK_33M_LPC_CPLD CLK_48M_BMC_CLK CLK_48M_BMC_CLKIN CLK_50M_BMC_NCSI CLK_50M_NIC1_NCSI CLK_50M_OE CLK_50M_OUT0 CLK_50M_OUT1 CLK_50M_OUT2 CLK_50M_OUT3 CLK_156M25_PHY_SRC_SEL CLK_LPC_OUT0 CLK_LPC_OUT1 CLK_LPC_OUT2 CLK_LPC_OUT3 CLK_MAC_TS_BIT_CLK0 CLK_MAC_TS_BIT_CLK1 CLK_MAC_TS_SYNC1 CLK_NIC1_XTAL1 CLK_NIC1_XTAL1_IN CLK_NIC1_XTAL2 CLK_NIC1_XTAL2_OUT CLK_OUT_BITS_OSCI CLK_PTP_1PPS_APLL1 CLK_PTP_1PPS_DPLL_BUFF CLK_PTP_1PPS_DPLL_OUT CLK_PTP_1PPS_DPLL_OUT1 CLK_PTP_1PPS_DPLL_TO_MAC CLK_PTP_1PPS_DPLL_TO_PHY1 CLK_PTP_1PPS_DPLL_TO_PHY3 CLK_PTP_1PPS_FRSYNC CLK_PTP_1PPS_MAC_TO_DPLL CLK_PTP_1PPS_MAC_TO_SMA CLK_PTP_1PPS_MFRSYNC CLK_PTP_4K_DPLL_OUT CLK_PTP_4K_DPLL_TO_MAC CLK_PTP_4K_DPLL_TO_PHY1 CLK_PTP_4K_DPLL_TO_PHY3 CLK_PTP_10M_MAC_TO_DPLL CLK_PTP_10M_MAC_TO_SMA CLKGEN_54M_XTAL_IN CLKGEN_54M_XTAL_OUT N70532709 N72863733 N73156286 N84741258 OSC_PCIE_25M_OE PD_COREPLL_BYP_CLK0 PD_COREPLL_BYP_CLK1 PD_MCUPLL_BYP_CLK0 PD_MCUPLL_BYP_CLK1 PD_NIF_LCPLL_BYP_CLK PD_NIFE_LCPLL0_BYP_CLK PD_NIFE_LCPLL1_BYP_CLK TCXO_NCG TCXO_OE TP_CLK_25M_PCIE_XTALOUT TP_JTAG_BITS_TCK TP_JTAG_CPU_TCK TP_JTAG_SMU_TCK TP_MAC_DDRA_PLL_CLK_MON TP_TCXO_REF_OUT
net group CLK_25M_MAC_COREPLL_DN: nets CLK_25M_MAC_COREPLL_DN N72722791 N72725483
net group CLK_25M_MAC_COREPLL_DP: nets CLK_25M_MAC_COREPLL_DP N72722789 N72725479
net group CLK_25M_MAC_MCUPLL_DN: nets CLK_25M_MAC_MCUPLL_DN N72722809 N72725499
net group CLK_25M_MAC_MCUPLL_DP: nets CLK_25M_MAC_MCUPLL_DP N72722811 N72725491
net group CLK_25M_MAC_TSPLL_DN: nets CLK_25M_MAC_TSPLL_DN N72722849 N72725515
net group CLK_25M_MAC_TSPLL_DP: nets CLK_25M_MAC_TSPLL_DP N72722851 N72725507
net group CLK_100M_MAC_DDRA_DN: nets CLK_100M_MAC_DDRA_DN N72722464 N72724116
net group CLK_100M_MAC_DDRA_DP: nets CLK_100M_MAC_DDRA_DP N72722462 N72724118
net group CLK_100M_MAC_DDRB_DN: nets CLK_100M_MAC_DDRB_DN N72722468 N72724122
net group CLK_100M_MAC_DDRB_DP: nets CLK_100M_MAC_DDRB_DP N72722466 N72724120
net group CLK_100M_MAC_DDRC_DN: nets CLK_100M_MAC_DDRC_DN N72722481 N72724126
net group CLK_100M_MAC_DDRC_DP: nets CLK_100M_MAC_DDRC_DP N72722479 N72724124
net group CLK_156M25_DPLL_REFCLK_DN: nets CLK_156M25_DPLL_REFCLK_DN CLK_156M25_PTP_REF_DN N70702948
net group CLK_156M25_DPLL_REFCLK_DP: nets CLK_156M25_DPLL_REFCLK_DP CLK_156M25_PTP_REF_DP N70702946
net group CLK_156M25_MAC_NIF_LCPLL_DN: nets CLK_156M25_MAC_NIF_LCPLL_DN CLK_156M25_OUT0_NIF_LCPLL_DN N84949005
net group CLK_156M25_MAC_NIF_LCPLL_DP: nets CLK_156M25_MAC_NIF_LCPLL_DP CLK_156M25_OUT0_NIF_LCPLL_DP N84948998
net group CLK_156M25_MAC_NIFE_LCPLL0_DN: nets CLK_156M25_MAC_NIFE_LCPLL0_DN CLK_156M25_OUT1_NIFE_LCPLL0_DN N84949054
net group CLK_156M25_MAC_NIFE_LCPLL0_DP: nets CLK_156M25_MAC_NIFE_LCPLL0_DP CLK_156M25_OUT1_NIFE_LCPLL0_DP N84949057
net group CLK_156M25_MAC_NIFE_LCPLL1_DN: nets CLK_156M25_MAC_NIFE_LCPLL1_DN CLK_156M25_OUT2_NIFE_LCPLL1_DN N84949110
net group CLK_156M25_MAC_NIFE_LCPLL1_DP: nets CLK_156M25_MAC_NIFE_LCPLL1_DP CLK_156M25_OUT2_NIFE_LCPLL1_DP N84949113
net group CLK_156M25_PHY1_DN: nets CLK_156M25_PHY1_DN CLK_156M25_PHY1_REFCLK_DN N73814194
net group CLK_156M25_PHY1_DP: nets CLK_156M25_PHY1_DP CLK_156M25_PHY1_REFCLK_DP N73814196
net group CLK_156M25_PHY3_REFCLK_DN: nets CLK_156M25_PHY3_REFCLK_DN N71582475 N73814180
net group CLK_156M25_PHY3_REFCLK_DP: nets CLK_156M25_PHY3_REFCLK_DP N71582478 N73814192
net group CLK_MAC_SRD_REFCLK_OUT0: nets CLK_MAC_SRD_REFCLK_OUT0 CLK_MAC_SYNCE_RCVD1_DP CLK_MAC_SYNCE_REFCLK1_DP
net group CLK_MAC_SRD_REFCLK_OUT1: nets CLK_MAC_SRD_REFCLK_OUT1 CLK_MAC_SYNCE_RCVD1_DN CLK_MAC_SYNCE_REFCLK1_DN
net group CLK_MAC_SRD_REFCLK_OUT2: nets CLK_MAC_SRD_REFCLK_OUT2 CLK_MAC_SYNCE_RCVD2_DP CLK_MAC_SYNCE_REFCLK2_DP
net group CLK_MAC_SRD_REFCLK_OUT3: nets CLK_MAC_SRD_REFCLK_OUT3 CLK_MAC_SYNCE_RCVD2_DN CLK_MAC_SYNCE_REFCLK2_DN
net group DDR3_BMC_ADD: nets DDR3_BMC_AD0 DDR3_BMC_AD1 DDR3_BMC_AD2 DDR3_BMC_AD3 DDR3_BMC_AD4 DDR3_BMC_AD5 DDR3_BMC_AD6 DDR3_BMC_AD7 DDR3_BMC_AD8 DDR3_BMC_AD9 DDR3_BMC_AD10 DDR3_BMC_AD11 DDR3_BMC_AD12 DDR3_BMC_AD13 DDR3_BMC_AD14 DDR3_BMC_BA0 DDR3_BMC_BA1 DDR3_BMC_BA2 DDR3_BMC_CAS_N DDR3_BMC_CKE DDR3_BMC_CS0_N DDR3_BMC_ODT DDR3_BMC_RAS_N DDR3_BMC_WE_N
net group DDR3_BMC_ADRESS: nets DDR3_BMC_ZQ
net group DDR3_BMC_DATE0_7: nets DDR3_BMC_DM0 DDR3_BMC_DQ0 DDR3_BMC_DQ1 DDR3_BMC_DQ2 DDR3_BMC_DQ3 DDR3_BMC_DQ4 DDR3_BMC_DQ5 DDR3_BMC_DQ6 DDR3_BMC_DQ7
net group DDR3_BMC_DATE8_15: nets DDR3_BMC_DM1 DDR3_BMC_DQ8 DDR3_BMC_DQ9 DDR3_BMC_DQ10 DDR3_BMC_DQ11 DDR3_BMC_DQ12 DDR3_BMC_DQ13 DDR3_BMC_DQ14 DDR3_BMC_DQ15
net group DDRA_DATA_0-7_MG: nets MAC_DDRA_DBI0_N MAC_DDRA_DQ00 MAC_DDRA_DQ01 MAC_DDRA_DQ02 MAC_DDRA_DQ03 MAC_DDRA_DQ04 MAC_DDRA_DQ05 MAC_DDRA_DQ06 MAC_DDRA_DQ07
net group DDRA_DATA_8-15_MG: nets MAC_DDRA_DBI1_N MAC_DDRA_DQ08 MAC_DDRA_DQ09 MAC_DDRA_DQ10 MAC_DDRA_DQ11 MAC_DDRA_DQ12 MAC_DDRA_DQ13 MAC_DDRA_DQ14 MAC_DDRA_DQ15
net group DDRA_DATA_16-23_MG: nets MAC_DDRA_DBI2_N MAC_DDRA_DQ16 MAC_DDRA_DQ17 MAC_DDRA_DQ18 MAC_DDRA_DQ19 MAC_DDRA_DQ20 MAC_DDRA_DQ21 MAC_DDRA_DQ22 MAC_DDRA_DQ23
net group DDRA_DATA_24-31_MG: nets MAC_DDRA_DBI3_N MAC_DDRA_DQ24 MAC_DDRA_DQ25 MAC_DDRA_DQ26 MAC_DDRA_DQ27 MAC_DDRA_DQ28 MAC_DDRA_DQ29 MAC_DDRA_DQ30 MAC_DDRA_DQ31
net group DDRB_DATA_0-7_MG: nets MAC_DDRB_DBI0_N MAC_DDRB_DQ00 MAC_DDRB_DQ01 MAC_DDRB_DQ02 MAC_DDRB_DQ03 MAC_DDRB_DQ04 MAC_DDRB_DQ05 MAC_DDRB_DQ06 MAC_DDRB_DQ07
net group DDRB_DATA_8-15_MG: nets MAC_DDRB_DBI1_N MAC_DDRB_DQ08 MAC_DDRB_DQ09 MAC_DDRB_DQ10 MAC_DDRB_DQ11 MAC_DDRB_DQ12 MAC_DDRB_DQ13 MAC_DDRB_DQ14 MAC_DDRB_DQ15
net group DDRB_DATA_16-23_MG: nets MAC_DDRB_DBI2_N MAC_DDRB_DQ16 MAC_DDRB_DQ17 MAC_DDRB_DQ18 MAC_DDRB_DQ19 MAC_DDRB_DQ20 MAC_DDRB_DQ21 MAC_DDRB_DQ22 MAC_DDRB_DQ23
net group DDRB_DATA_24-31_MG: nets MAC_DDRB_DBI3_N MAC_DDRB_DQ24 MAC_DDRB_DQ25 MAC_DDRB_DQ26 MAC_DDRB_DQ27 MAC_DDRB_DQ28 MAC_DDRB_DQ29 MAC_DDRB_DQ30 MAC_DDRB_DQ31
net group DDRC_DATA_0-7_MG: nets MAC_DDRC_DBI0_N MAC_DDRC_DQ00 MAC_DDRC_DQ01 MAC_DDRC_DQ02 MAC_DDRC_DQ03 MAC_DDRC_DQ04 MAC_DDRC_DQ05 MAC_DDRC_DQ06 MAC_DDRC_DQ07
net group DDRC_DATA_8-15_MG: nets MAC_DDRC_DBI1_N MAC_DDRC_DQ08 MAC_DDRC_DQ09 MAC_DDRC_DQ10 MAC_DDRC_DQ11 MAC_DDRC_DQ12 MAC_DDRC_DQ13 MAC_DDRC_DQ14 MAC_DDRC_DQ15
net group DDRC_DATA_16-23_MG: nets MAC_DDRC_DBI2_N MAC_DDRC_DQ16 MAC_DDRC_DQ17 MAC_DDRC_DQ18 MAC_DDRC_DQ19 MAC_DDRC_DQ20 MAC_DDRC_DQ21 MAC_DDRC_DQ22 MAC_DDRC_DQ23
net group DDRC_DATA_24-31_MG: nets MAC_DDRC_DBI3_N MAC_DDRC_DQ24 MAC_DDRC_DQ25 MAC_DDRC_DQ26 MAC_DDRC_DQ27 MAC_DDRC_DQ28 MAC_DDRC_DQ29 MAC_DDRC_DQ30 MAC_DDRC_DQ31
net group P1V0_SW: nets N58331367
net group POWER: nets DDR3_DRAM_MVREF ISHARE ISHARE_R MAC_DDRA0_CHIP_ZQ MAC_DDRA0_VREFCA MAC_DDRA1_CHIP_ZQ MAC_DDRA1_VREFCA MAC_DDRA_RES_NEG MAC_DDRA_RES_POS MAC_DDRA_RES_VDD MAC_DDRA_RES_VSS MAC_DDRB0_CHIP_ZQ MAC_DDRB0_VREFCA MAC_DDRB1_CHIP_ZQ MAC_DDRB1_VREFCA MAC_DDRC0_CHIP_ZQ MAC_DDRC0_VREFCA MAC_DDRC1_CHIP_ZQ MAC_DDRC1_VREFCA MAC_DDRC_RES_NEG MAC_DDRC_RES_POS MAC_DDRC_RES_VDD MAC_DDRC_RES_VSS MAC_MCUPLL_LOCK N64116787 N64116818 N64130082 N64130635 N64131592 N65289036 N65289586 N66144514 N66148865 N66362177 N66362186 N70233459 N70703858 N70703933 N70911322 N70911698 N72619067 N73054323 N73156284 N74679075 N74680300 N74682687 N74683537 N74685275 N74685283 N74685349 N74685355 N74685391 N74685429 N74685493 N74685644 N74687466 N74687472 N74690205 N74690227 N74690437 N74690459 N75511000 N75609157 N82446790 N84148690 N84432227 N855994741 P1V0_BOOT P1V0_BP P1V0_DDR_BST P1V0_DDR_CS P1V0_DDR_EN P1V0_DDR_FB P1V0_DDR_FB_IN P1V0_DDR_FB_IN_R P1V0_DDR_FB_R P1V0_DDR_MARGIN_HI P1V0_DDR_MARGIN_LO P1V0_DDR_MODE P1V0_DDR_PG P1V0_DDR_REF P1V0_DDR_VCC P1V0_EN P1V0_ILIM P1V0_MARGIN_HI P1V0_MARGIN_LO P1V0_MODE P1V0_PG P1V0_RAMP P1V0_RSN P1V0_RSP P1V0_RSP_R P1V0_RSP_R1 P1V0_RSP_R1R P1V0_RT P1V0_SN P1V0_SS P1V0_VDD P1V0_VSEL P1V2_BST P1V2_CS P1V2_EN P1V2_FB P1V2_FB_IN P1V2_FB_IN_R P1V2_FB_R P1V2_MODE P1V2_PG P1V2_REF P1V2_VCC P1V05_CPU P1V8_EN P1V8_EN_R P1V8_FB_IN P1V8_FB_IN_R P1V8_PG P1V8_SS P1V8_VBST P1V8_VFB P1V8_VFB_R P1V25_BST P1V25_CS P1V25_EN P1V25_EN_R P1V25_FB P1V25_FB_IN P1V25_FB_IN_R P1V25_FB_R P1V25_MODE P1V25_PG P1V25_REF P1V25_VCC P1V26_BMC_EN P1V26_BMC_FB P1V26_BMC_FB_IN P1V26_BMC_PG P1V538_BMC_EN P1V538_BMC_FB P1V538_BMC_FB_IN P1V538_BMC_PG P2V5_EN P2V5_PG P2V5_SS P2V5_VBST P2V5_VFB P2V5_VFB_IN P2V5_VFB_IN_R P2V5_VFB_R P3V3_BMC_EN P3V3_BMC_FB P3V3_BMC_IN P3V3_BMC_PG P3V3_BOOT P3V3_BOOT2 P3V3_BP P3V3_BP2 P3V3_EN P3V3_HWM_V33A P3V3_HWM_V33FB P3V3_ILIM P3V3_ILIM2 P3V3_MODE P3V3_MODE2 P3V3_OCXO_EN P3V3_OCXO_FB P3V3_OCXO_PG P3V3_OCXO_SS P3V3_PG P3V3_RAMP P3V3_RAMP2 P3V3_RSN P3V3_RSN2 P3V3_RSP P3V3_RSP2 P3V3_RSP2_R1 P3V3_RSP_R P3V3_RSP_R1 P3V3_RSP_R1R P3V3_RT P3V3_RT2 P3V3_SFP_DISCHARGE_P00 P3V3_SFP_DISCHARGE_P01 P3V3_SFP_DISCHARGE_P02 P3V3_SFP_DISCHARGE_P03 P3V3_SFP_DISCHARGE_P04 P3V3_SFP_DISCHARGE_P05 P3V3_SFP_DISCHARGE_P06 P3V3_SFP_DISCHARGE_P07 P3V3_SFP_DISCHARGE_P08 P3V3_SFP_DISCHARGE_P09 P3V3_SFP_DISCHARGE_P10 P3V3_SFP_DISCHARGE_P11 P3V3_SFP_DISCHARGE_P12 P3V3_SFP_DISCHARGE_P13 P3V3_SFP_DISCHARGE_P14 P3V3_SFP_DISCHARGE_P15 P3V3_SFP_DISCHARGE_P16 P3V3_SFP_DISCHARGE_P17 P3V3_SFP_DISCHARGE_P18 P3V3_SFP_DISCHARGE_P19 P3V3_SFP_DISCHARGE_P20 P3V3_SFP_DISCHARGE_P21 P3V3_SFP_DISCHARGE_P22 P3V3_SFP_DISCHARGE_P23 P3V3_SFP_DISCHARGE_P24 P3V3_SFP_DISCHARGE_P25 P3V3_SFP_DISCHARGE_P26 P3V3_SFP_DISCHARGE_P27 P3V3_SFP_DISCHARGE_P32 P3V3_SFP_DISCHARGE_P33 P3V3_SN P3V3_SN2 P3V3_SS P3V3_SS2 P3V3_VBAT P3V3_VDD P3V3_VDD2 P3V3_VSEL P3V3_VSEL2 P5V0_EN P5V0_FB_IN P5V0_FB_IN_R P5V0_PG P5V0_SS P5V0_VBST P5V0_VFB P5V0_VFB_R P10V_H2_EN_R P10V_H2_FB P10V_H2_MODE P10V_H2_SS/TR P10V_H2_VMG-LOW1_R P10V_H2_VMG-LOW2_R P10V_H2_VOS P10V_H2_VOS_R QSFP28_P1_VCC QSFP28_P1_VCCRX QSFP28_P1_VCCTX QSFP28_P2_VCC QSFP28_P2_VCCRX SYNC SYNC_R VCC_GNSS_RF VDD_CORE_ADDR_TRISE VDD_CORE_BOOT1 VDD_CORE_BOOT2 VDD_CORE_BOOTR1 VDD_CORE_BOOTR2 VDD_CORE_COMP VDD_CORE_COMP_RC VDD_CORE_CSP1 VDD_CORE_CSP2 VDD_CORE_CSP3 VDD_CORE_EN-FCCM1 VDD_CORE_EN-FCCM2 VDD_CORE_ENABLE VDD_CORE_F-MAX VDD_CORE_IMON VDD_CORE_IMON_R VDD_CORE_ISUM VDD_CORE_LSET1 VDD_CORE_LSET2 VDD_CORE_O-USR VDD_CORE_OCL-R VDD_CORE_PMB_ALERT_L VDD_CORE_PMB_CLK VDD_CORE_PMB_DIO VDD_CORE_PWM1 VDD_CORE_PWM1_R VDD_CORE_PWM2 VDD_CORE_PWM2_R VDD_CORE_RESET_L VDD_CORE_SKIP#NVM VDD_CORE_SLEW_MODE VDD_CORE_TSEN VDD_CORE_V3R3 VDD_CORE_V5 VDD_CORE_VBOOT VDD_CORE_VDD1 VDD_CORE_VDD2 VDD_CORE_VIN VDD_CORE_VR_HOT_L VDD_CORE_VSP_R VFLT_P3V3_1PPS_BUFF VFLT_P3V3_1PPS_BUFF2 VFLT_P3V3_4K_BUFF VFLT_P3V3_BMC_ADCAV33 VFLT_P3V3_BMC_DACV33 VFLT_P3V3_BMC_MPLLAV33 VFLT_P3V3_BMC_OSC VFLT_P3V3_CPLD_OSC VFLT_P3V3_DDR_CLK_100MHZ VFLT_P3V3_DDR_OSC_100MHZ VFLT_P3V3_GNSS_VBCKP VFLT_P3V3_JA_VDDS VFLT_P3V3_NIC1_AVDD VFLT_P3V3_NIC1_OSC VFLT_P3V3_PTP_OSC VFLT_VP1P8_MAC_VDDO VMG_BMC_HEATER_EN VMG_BMC_HEATER_HIGH VMG_BMC_HEATER_HIGH_BMC VMG_BMC_HEATER_HIGH_HWM VMG_BMC_HEATER_LOW VMG_BMC_HEATER_LOW_BMC VMG_BMC_HEATER_LOW_HWM VMON_BMC_HEATER VMON_HWM_P1V0_PHY_VIN VMON_HWM_P1V2_VIN VMON_HWM_P1V8_VIN VMON_HWM_P1V25_VIN VMON_HWM_P3V3_VIN VMON_HWM_P12V_VIN VMON_HWM_TEMP_BMC VMON_HWM_TEMP_CPU VMON_HWM_TEMP_HEATER VMON_HWM_TEMP_MAC VMON_HWM_TEMP_PHY3 VMON_HWM_VCORE_VIN VMON_P1V0_DDR_VIN VMON_P2V5_VIN VMON_P5V_SB_VIN VMON_P12V_VIN VMON_TEMP_OCXO VSHARE VSHARE_R VTT_DDR_REFIN VTT_DDR_REFOUT XTAL_SHIELD
net group SPI: nets NIC1_CAP_BOT NIC1_CAP_TOP NIC1_DEV_OFF_N

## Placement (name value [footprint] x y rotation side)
BAT1  BB3320E-D1  [BA-D23_1X5_8-3S0]  146.53 147.86 0 top
C3  0.1uF  [S-C-0402]  208.36 104.5 0 bottom
C4  10uF  [C-0603S0]  249.26 117.23 180 bottom
C5  0.1uF  [S-C-0402]  250.53 117.39 180 bottom
C6  0.1uF  [S-C-0402]  246.83 154.7 270 bottom
C7  10uF  [C-0603S0]  247.08 153.51 270 bottom
C8  0.1uF  [S-C-0402]  263.09 138.38 270 bottom
C9  0.1uF  [S-C-0402]  262.38 126.93 90 bottom
C10  0.1uF  [S-C-0402]  207.26 164.21 180 bottom
C11  0.1uF  [S-C-0402]  219.46 163.7 0 bottom
C12  0.1uF  [S-C-0402]  216.36 127.5 0 bottom
C13  1uF  [S-C-0402]  204.86 129 90 bottom
C14  0.1uF  [S-C-0402]  222.86 123 90 bottom
C15  1uF  [S-C-0402]  206.86 129 90 bottom
C16  0.1uF  [S-C-0402]  222.36 125.5 0 bottom
C17  1uF  [S-C-0402]  212.36 126.5 0 bottom
C18  0.1uF  [S-C-0402]  223.36 127.5 180 bottom
C19  10uF  [C-0603S0]  181.34 137.21 90 top
C20  0.1uF  [S-C-0402]  238.85 115.59 0 bottom
C21  1uF  [S-C-0402]  206.36 127.5 180 bottom
C22  0.1uF  [S-C-0402]  223.36 125.5 0 bottom
C23  1uF  [S-C-0402]  213.36 128.5 180 bottom
C24  10uF  [C-0603S0]  192.43 145.57 270 top
C25  10uF  [C-0603S0]  220.16 153.51 270 bottom
C26  0.1uF  [S-C-0402]  207.73 154.7 270 bottom
C27  0.1uF  [S-C-0402]  198.02 168.27 0 bottom
C28  10uF  [C-0603S0]  207.89 153.43 270 bottom
C29  0.1uF  [S-C-0402]  219.91 154.7 270 bottom
C30  0.1uF  [S-C-0402]  210.58 167.26 0 bottom
C31  0.1uF  [S-C-0402]  246.38 163.96 180 bottom
C32  0.1uF  [S-C-0402]  234.31 164.21 180 bottom
C33  0.1uF  [S-C-0402]  212.36 128.5 180 bottom
C34  1uF  [S-C-0402]  215.36 127.5 0 bottom
C35  0.1uF  [S-C-0402]  207.36 127.5 180 bottom
C36  1uF  [S-C-0402]  214.36 127.5 180 bottom
C37  10uF  [C-0603S0]  192.15 147.88 0 top
C38  10uF  [C-0603S0]  249.34 128.8 180 bottom
C39  0.1uF  [S-C-0402]  237.14 166.21 90 bottom
C40  0.1uF  [S-C-0402]  234.66 154.7 270 bottom
C41  10uF  [C-0603S0]  234.81 153.43 270 bottom
C42  0.1uF  [S-C-0402]  224.98 166.52 90 bottom
C43  0.1uF  [S-C-0402]  250.53 129.05 180 bottom
C44  0.1uF  [S-C-0402]  260.1 117.98 90 bottom
C45  0.1uF  [S-C-0402]  260.02 129.54 90 bottom
C46  0.1uF  [S-C-0402]  205.36 127.5 180 bottom
C47  1uF  [S-C-0402]  221.36 123.5 0 bottom
C48  0.1uF  [S-C-0402]  222.86 124 90 bottom
C49  1uF  [S-C-0402]  208.36 128.5 180 bottom
C50  10uF  [C-0603S0]  214.28 129.88 225 bottom
C51  330uF  [C-TAN-S7_3X4_3-H2]  260.16 165.25 90 top
C52  330uF  [C-TAN-S7_3X4_3-H2]  235.46 136.2 180 bottom
C53  47uF  [C-0805-H1_35]  222.02 139.68 90 bottom
C54  1uF  [S-C-0402]  229.37 137.49 0 bottom
C55  0.1uF  [S-C-0402]  224.36 133.5 180 bottom
C56  0.1uF  [S-C-0402]  223.36 137.5 180 bottom
C57  1nF  [S-C-0402]  231.36 129.5 0 bottom
C58  0.1uF  [S-C-0402]  231.36 123.5 180 bottom
C59  1uF  [S-C-0402]  238.35 153.64 270 bottom
C60  0.1uF  [S-C-0402]  234.15 158.26 0 bottom
C61  0.1uF  [S-C-0402]  234.15 160.04 180 bottom
C62  1nF  [S-C-0402]  231.36 135.5 0 bottom
C63  0.1uF  [S-C-0402]  232.71 160.71 90 bottom
C64  1uF  [S-C-0402]  237.29 159.49 90 bottom
C65  0.1uF  [S-C-0402]  237.38 160.54 270 bottom
C66  0.1uF  [S-C-0402]  244.76 153.64 270 bottom
C67  1nF  [S-C-0402]  249.47 125.86 180 bottom
C68  0.1uF  [S-C-0402]  244.76 160.84 90 bottom
C69  1uF  [S-C-0402]  237.07 156.54 90 bottom
C70  0.1uF  [S-C-0402]  252.87 126.62 90 bottom
C71  0.1uF  [S-C-0402]  252.49 138.62 180 bottom
C72  1nF  [S-C-0402]  251.55 117.39 180 bottom
C73  0.1uF  [S-C-0402]  225.36 135.5 180 bottom
C74  330uF  [C-TAN-S7_3X4_3-H2]  250.42 156.35 0 top
C75  47uF  [C-0805-H1_35]  220.23 170.61 270 top
C76  1uF  [S-C-0402]  249.47 131.13 0 bottom
C77  0.1uF  [S-C-0402]  255.87 117.89 90 bottom
C78  0.1uF  [S-C-0402]  256.54 119.34 0 bottom
C79  1nF  [S-C-0402]  256.68 125.06 0 bottom
C80  0.1uF  [S-C-0402]  255.42 138.57 180 bottom
C81  1uF  [S-C-0402]  249.47 119.46 0 bottom
C82  0.1uF  [S-C-0402]  257.8 136.66 90 bottom
C83  0.1uF  [S-C-0402]  255.87 129.56 90 bottom
C84  1nF  [S-C-0402]  255.77 126.52 270 bottom
C85  0.1uF  [S-C-0402]  256.67 131.13 0 bottom
C86  1uF  [S-C-0402]  241.94 159.89 270 bottom
C87  0.1uF  [S-C-0402]  256.37 138.6 180 bottom
C88  0.1uF  [S-C-0402]  200.37 133.5 0 bottom
C89  1nF  [S-C-0402]  199.26 153.64 270 bottom
C90  0.1uF  [S-C-0402]  197.99 156.47 270 bottom
C91  1uF  [S-C-0402]  249.47 137.53 180 bottom
C92  0.1uF  [S-C-0402]  198.37 135.5 0 bottom
C93  0.1uF  [S-C-0402]  202.36 131.5 0 bottom
C94  1nF  [S-C-0402]  198.48 159.59 0 bottom
C95  0.1uF  [S-C-0402]  204.37 135.5 0 bottom
C96  330uF  [C-TAN-S7_3X4_3-H2]  262.76 142.37 90 top
C97  47uF  [C-0805-H1_35]  227.6 139.68 90 bottom
C98  1uF  [S-C-0402]  256.54 121.21 0 bottom
C99  0.1uF  [S-C-0402]  210.86 131 90 bottom
C100  0.1uF  [S-C-0402]  217.83 160.84 90 bottom
C101  1nF  [S-C-0402]  200.05 161.9 0 bottom
C102  0.1uF  [S-C-0402]  215.36 137.5 0 bottom
C103  1uF  [S-C-0402]  196.36 137.5 180 bottom
C104  0.1uF  [S-C-0402]  220.36 137.5 180 bottom
C105  0.1uF  [S-C-0402]  221.37 133.5 180 bottom
C106  1nF  [S-C-0402]  205.37 131.5 180 bottom
C107  0.1uF  [S-C-0402]  222.36 129.5 180 bottom
C108  1uF  [S-C-0402]  203.91 160.71 90 bottom
C109  0.1uF  [S-C-0402]  219.37 129.5 180 bottom
C110  0.1uF  [S-C-0402]  223.37 131.5 180 bottom
C111  1nF  [S-C-0402]  201.36 137.5 0 bottom
C112  0.1uF  [S-C-0402]  219.91 155.72 90 bottom
C113  1uF  [S-C-0402]  198.35 137.5 0 bottom
C114  0.1uF  [S-C-0402]  219.4 160.04 180 bottom
C115  0.1uF  [S-C-0402]  219.4 158.26 0 bottom
C116  1nF  [S-C-0402]  204.37 137.5 0 bottom
C117  0.1uF  [S-C-0402]  225.36 129.5 180 bottom
